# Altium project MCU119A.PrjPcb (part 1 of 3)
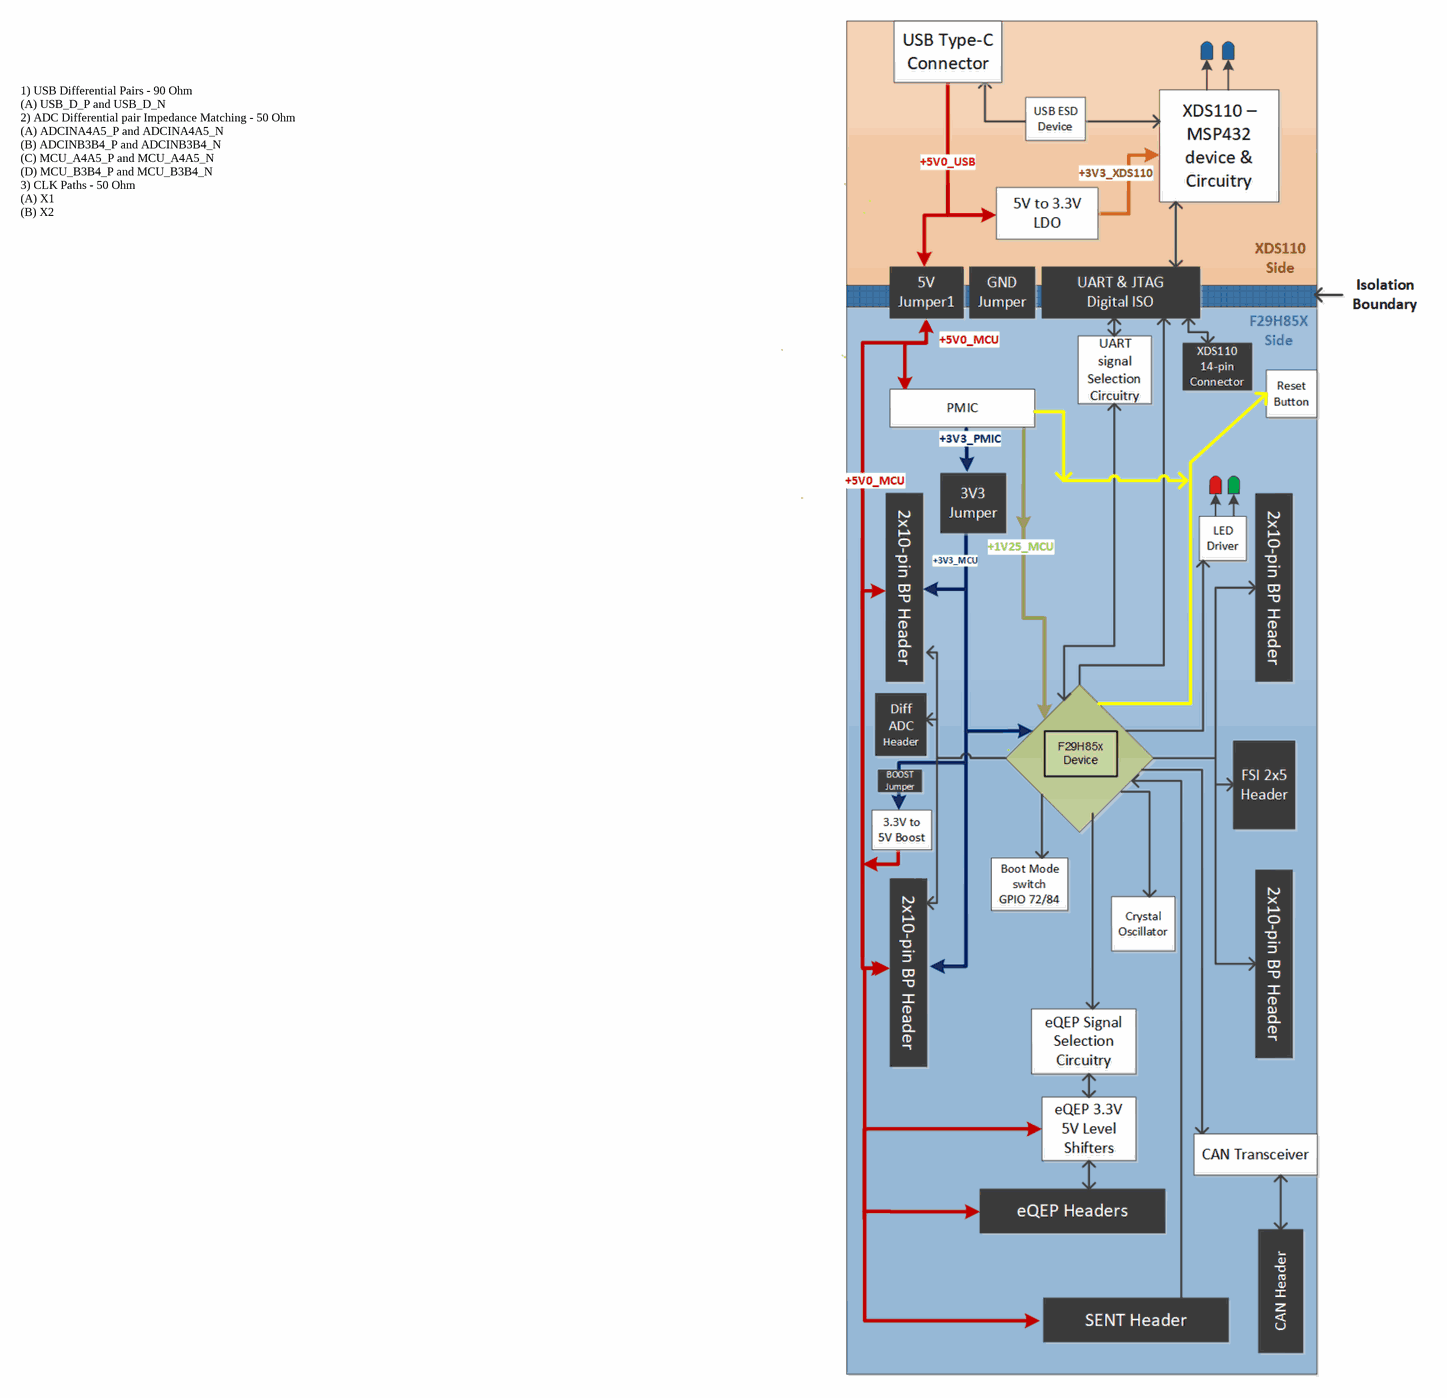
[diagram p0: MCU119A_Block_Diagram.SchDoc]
CopyrightYear: 2024; DrawnBy: Susmitha Bumadi; EVM_orderable: LAUNCHXL-F29H85X; PCB_Layout: a0509580; PCB_Rev: A; PRJ_Customer: Public Release; PRJ_Engineer: Susmitha Bumadi; PRJ_Number: MCU119; PRJ_Title: LAUNCHXL-F29H85X; SCH_Rev: A; TechSupport: http://www.ti.com/support; TID: N/A
8 sheets, 317 parts. Net scope: global (net labels, ports and power ports of the same name join across sheets).
Board file: MCU119A.PcbDoc
Sheets:
  MCU119A_Block_Diagram.SchDoc
  MCU119A_Connectors.SchDoc
  MCU119A_F29H85X_Device.SchDoc
  MCU119A_ADC.SchDoc
  MCU119A_USB_and_Power.SchDoc
  MCU119A_XDS110_MCU.SchDoc
  MCU119A_AltRouting_Misc.SchDoc
  MCU119A_Hardware.SchDoc

## Sheet MCU119A_Block_Diagram.SchDoc
size 431 x 279 mm; Date: Not shown in title block; ApprovedBy: Not shown in title block; CheckedBy: Not shown in title block; Author: Not shown in title block; CompanyName: Not shown in title block; Engineer: Not shown in title block; Organization: Not shown in title block; Address1: Not shown in title block; Address2: Not shown in title block; Address3: Not shown in title block; Address4: Not shown in title block; DocumentNumber: 1; Revision: Use project parameter SCH_Rev; SheetNumber: 1; SheetTotal: 8; PageSetup: Record=PageOptions¦CenterHorizontal=True¦CenterVertical=True¦PrintScale=1.00¦XCorrection=1.00¦YCorrection=1.00¦PrintKind=0¦BorderSize=5000000¦LeftOffset=0¦BottomOffset=0¦Orientation=2¦PaperLength=1000¦PaperWidth=1000¦Scale=100¦PaperSource=15¦PrintQuality=600¦MediaType=1¦DitherType=10¦PaperKind=Letter¦PrintScaleMode=1

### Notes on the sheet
- 1) USB Differential Pairs - 90 Ohm
  (A) USB_D_P and USB_D_N
  2) ADC Differential pair Impedance Matching - 50 Ohm
  (A) ADCINA4A5_P and ADCINA4A5_N
  (B) ADCINB3B4_P and ADCINB3B4_N
  (C) MCU_A4A5_P and MCU_A4A5_N
  (D) MCU_B3B4_P and MCU_B3B4_N
  3) CLK Paths - 50 Ohm
  (A) X1
  (B) X2

## Sheet MCU119A_Connectors.SchDoc
size 431 x 279 mm; Date: Not shown in title block; ApprovedBy: Not shown in title block; CheckedBy: Not shown in title block; Author: Not shown in title block; CompanyName: Not shown in title block; Engineer: Not shown in title block; Organization: Not shown in title block; Address1: Not shown in title block; Address2: Not shown in title block; Address3: Not shown in title block; Address4: Not shown in title block; DocumentNumber: 2; Revision: Use project parameter SCH_Rev; SheetNumber: 2; SheetTotal: 8; PageSetup: Record=PageOptions¦CenterHorizontal=True¦CenterVertical=True¦PrintScale=1.00¦XCorrection=1.00¦YCorrection=1.00¦PrintKind=0¦BorderSize=5000000¦LeftOffset=0¦BottomOffset=0¦Orientation=2¦PaperLength=1000¦PaperWidth=1000¦Scale=100¦PaperSource=15¦PrintQuality=600¦MediaType=1¦DitherType=10¦PaperKind=Letter¦PrintScaleMode=1
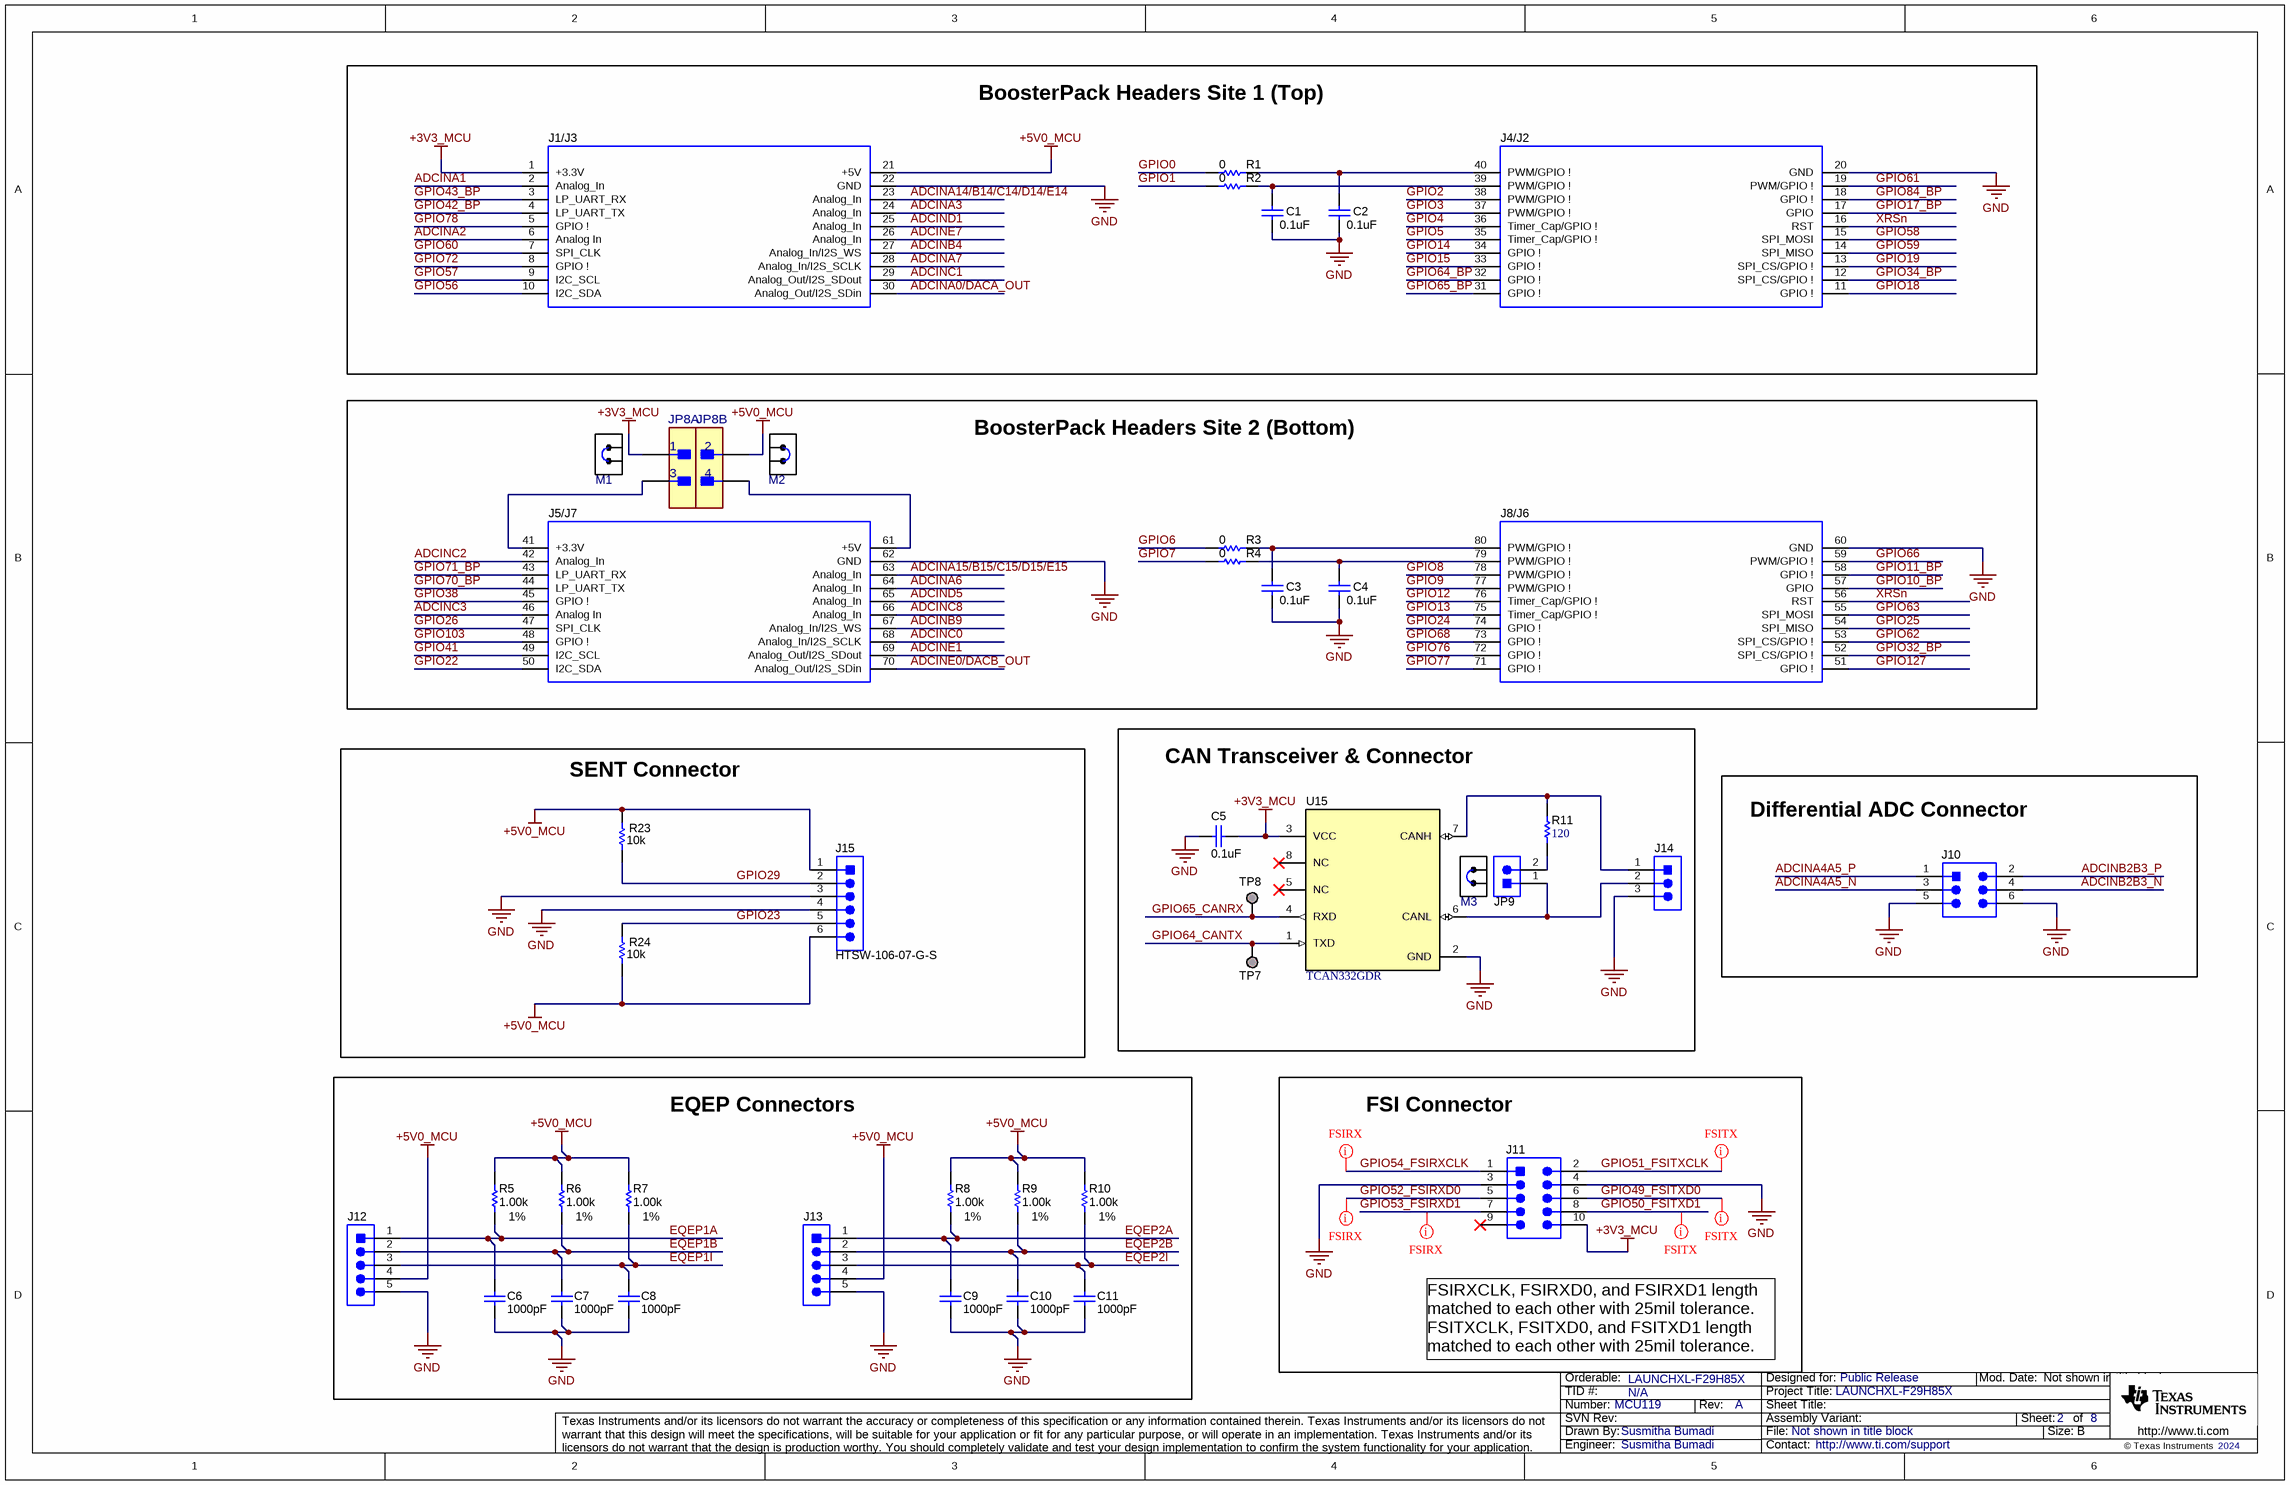
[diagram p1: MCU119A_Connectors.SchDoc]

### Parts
C1  ValueDisplayed: 0.1uF  [0402]  (hidden comment: 885012205037)
C2  ValueDisplayed: 0.1uF  [0402]  (hidden comment: 885012205037)
C3  ValueDisplayed: 0.1uF  [0402]  (hidden comment: 885012205037)
C4  ValueDisplayed: 0.1uF  [0402]  (hidden comment: 885012205037)
C5  ValueDisplayed: 0.1uF  [0402]  (hidden comment: 885012205037)
C6  ValueDisplayed: 1000pF  [0402]  (hidden comment: 885012205061)
C7  ValueDisplayed: 1000pF  [0402]  (hidden comment: 885012205061)
C8  ValueDisplayed: 1000pF  [0402]  (hidden comment: 885012205061)
C9  ValueDisplayed: 1000pF  [0402]  (hidden comment: 885012205061)
C10  ValueDisplayed: 1000pF  [0402]  (hidden comment: 885012205061)
C11  ValueDisplayed: 1000pF  [0402]  (hidden comment: 885012205061)
J1/J3  SSQ-110-03-T-D  [BoosterPack_40pin_J1J3]  (value not drawn)
J4/J2  SSQ-110-03-T-D  [BoosterPack_40pin_J2J4]  (value not drawn)
J5/J7  SSQ-110-03-T-D  [BoosterPack_40pin_J5J7]  (value not drawn)
J8/J6  SSQ-110-03-T-D  [BoosterPack_40pin_J6J8]  (value not drawn)
J10  61300621121  [Wurth_61300621121]  (value not drawn)
J11  61301021121  [WURTH_61301021121]  (value not drawn)
J12  61300511121  [Wurth_61300511121]  (value not drawn)
J13  61300511121  [Wurth_61300511121]  (value not drawn)
J14  61300311121  [WURTH_61300311121]  (value not drawn)
J15  HTSW-106-07-G-S  [FP-HTSW-106-07-G-S_HDR6-MFG]
JP8  61300421121  [FP-61300421121_HDR4-MFG]  (value not drawn)  (parts A,B of 2)
JP9  61300211121  [WURTH_61300211121]  (value not drawn)
M1  60900213421  [Wurth_60900213421]  (value not drawn)
M2  60900213421  [Wurth_60900213421]  (value not drawn)
M3  60900213421  [Wurth_60900213421]  (value not drawn)
R1  ValueDisplayed: 0  [0603]  (hidden comment: ERJ-3GEY0R00V)
R2  ValueDisplayed: 0  [0603]  (hidden comment: ERJ-3GEY0R00V)
R3  ValueDisplayed: 0  [0603]  (hidden comment: ERJ-3GEY0R00V)
R4  ValueDisplayed: 0  [0603]  (hidden comment: ERJ-3GEY0R00V)
R5  ValueDisplayed: 1.00k  Value1: 1%  [0402]  (hidden comment: CRCW04021K00FKED)
R6  ValueDisplayed: 1.00k  Value1: 1%  [0402]  (hidden comment: CRCW04021K00FKED)
R7  ValueDisplayed: 1.00k  Value1: 1%  [0402]  (hidden comment: CRCW04021K00FKED)
R8  ValueDisplayed: 1.00k  Value1: 1%  [0402]  (hidden comment: CRCW04021K00FKED)
R9  ValueDisplayed: 1.00k  Value1: 1%  [0402]  (hidden comment: CRCW04021K00FKED)
R10  ValueDisplayed: 1.00k  Value1: 1%  [0402]  (hidden comment: CRCW04021K00FKED)
R11  ValueDisplayed: 120  [0603]  (hidden comment: RC0603FR-07120RL)
R23  ValueDisplayed: 10k  [0402]  (hidden comment: CRCW040210K0JNED)
R24  ValueDisplayed: 10k  [0402]  (hidden comment: CRCW040210K0JNED)
TP7  TESTPOINT  [TP_50MIL-25MILHOLE]  (value not drawn)  (no BOM)
TP8  TESTPOINT  [TP_50MIL-25MILHOLE]  (value not drawn)  (no BOM)
U15  TCAN332GDR  [D0008A_N]

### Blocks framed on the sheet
BoosterPack Headers Site 1 (Top): C1 C2 J1/J3 J4/J2 R1 R2
BoosterPack Headers Site 2 (Bottom): C3 C4 J5/J7 J8/J6 JP8 M1 M2 R3 R4
SENT Connector: J15 R23 R24
CAN Transceiver & Connector: C5 J14 JP9 M3 R11 TP7 TP8 U15
Differential ADC Connector: J10
EQEP Connectors: C6-C11 J12 J13 R5-R10
FSI Connector: J11

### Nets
+3V3_MCU: C5.2 J1/J3.1(+3.3V) J11.10 JP8.1 U15.3(VCC)
+5V0_MCU: J1/J3.21(+5V) J12.4 J13.4 J15.1 J15.6 JP8.2 R5.2 R6.2 R7.2 R8.2 R9.2 R10.2 R23.2 R24.1
GND: C1.2 C2.2 C3.2 C4.2 C5.1 C6.2 C7.2 C8.2 C9.2 C10.2 C11.2 J1/J3.22(GND) J4/J2.20(GND) J5/J7.62(GND) J8/J6.60(GND) J10.5 J10.6 J11.3 J11.4 J12.5 J13.5 J14.3 J15.3 J15.4 U15.2(GND)
ADCINA0/DACA_OUT: J1/J3.30(Analog_Out/I2S_SDin)
ADCINA1: J1/J3.2(Analog_In)
ADCINA2: J1/J3.6(Analog_In)
ADCINA3: J1/J3.24(Analog_In)
ADCINA4A5_N: J10.3
ADCINA4A5_P: J10.1
ADCINA6: J5/J7.64(Analog_In)
ADCINA7: J1/J3.28(Analog_In/I2S_SCLK)
ADCINA14/B14/C14/D14/E14: J1/J3.23(Analog_In)
ADCINA15/B15/C15/D15/E15: J5/J7.63(Analog_In)
ADCINB2B3_N: J10.4
ADCINB2B3_P: J10.2
ADCINB4: J1/J3.27(Analog_In/I2S_WS)
ADCINB9: J5/J7.67(Analog_In/I2S_WS)
ADCINC0: J5/J7.68(Analog_In/I2S_SCLK)
ADCINC1: J1/J3.29(Analog_Out/I2S_SDout)
ADCINC2: J5/J7.42(Analog_In)
ADCINC3: J5/J7.46(Analog_In)
ADCINC8: J5/J7.66(Analog_In)
ADCIND1: J1/J3.25(Analog_In)
ADCIND5: J5/J7.65(Analog_In)
ADCINE0/DACB_OUT: J5/J7.70(Analog_Out/I2S_SDin)
ADCINE1: J5/J7.69(Analog_Out/I2S_SDout)
ADCINE7: J1/J3.26(Analog_In)
EQEP1A: C6.1 J12.1 R5.1
EQEP1B: C7.1 J12.2 R6.1
EQEP1I: C8.1 J12.3 R7.1
EQEP2A: C9.1 J13.1 R8.1
EQEP2B: C10.1 J13.2 R9.1
EQEP2I: C11.1 J13.3 R10.1
GPIO0: R1.2
GPIO1: R2.2
GPIO2: J4/J2.38(PWM/GPIO_!)
GPIO3: J4/J2.37(PWM/GPIO_!)
GPIO4: J4/J2.36(Timer_Cap/GPIO_!)
GPIO5: J4/J2.35(Timer_Cap/GPIO_!)
GPIO6: R3.2
GPIO7: R4.2
GPIO8: J8/J6.78(PWM/GPIO_!)
GPIO9: J8/J6.77(PWM/GPIO_!)
GPIO10_BP: J8/J6.57(GPIO)
GPIO11_BP: J8/J6.58(GPIO_!)
GPIO12: J8/J6.76(Timer_Cap/GPIO_!)
GPIO13: J8/J6.75(Timer_Cap/GPIO_!)
GPIO14: J4/J2.34(GPIO_!)
GPIO15: J4/J2.33(GPIO_!)
GPIO17_BP: J4/J2.17(GPIO)
GPIO18: J4/J2.11(GPIO_!)
GPIO19: J4/J2.13(SPI_CS/GPIO_!)
GPIO22: J5/J7.50(I2C_SDA)
GPIO23: J15.5 R24.2
GPIO24: J8/J6.74(GPIO_!)
GPIO25: J8/J6.54(SPI_MISO)
GPIO26: J5/J7.47(SPI_CLK)
GPIO29: J15.2 R23.1
GPIO32_BP: J8/J6.52(SPI_CS/GPIO_!)
GPIO34_BP: J4/J2.12(SPI_CS/GPIO_!)
GPIO38: J5/J7.45(GPIO_!)
GPIO41: J5/J7.49(I2C_SCL)
GPIO42_BP: J1/J3.4(LP_UART_TX)
GPIO43_BP: J1/J3.3(LP_UART_RX)
GPIO49_FSITXD0: J11.6
GPIO50_FSITXD1: J11.8
GPIO51_FSITXCLK: J11.2
GPIO52_FSIRXD0: J11.5
GPIO53_FSIRXD1: J11.7
GPIO54_FSIRXCLK: J11.1
GPIO56: J1/J3.10(I2C_SDA)
GPIO57: J1/J3.9(I2C_SCL)
GPIO58: J4/J2.15(SPI_MOSI)
GPIO59: J4/J2.14(SPI_MISO)
GPIO60: J1/J3.7(SPI_CLK)
GPIO61: J4/J2.19(PWM/GPIO_!)
GPIO62: J8/J6.53(SPI_CS/GPIO_!)
GPIO63: J8/J6.55(SPI_MOSI)
GPIO64_BP: J4/J2.32(GPIO_!)
GPIO64_CANTX: TP7.1 U15.1(TXD)
GPIO65_BP: J4/J2.31(GPIO_!)
GPIO65_CANRX: TP8.1 U15.4(RXD)
GPIO66: J8/J6.59(PWM/GPIO_!)
GPIO68: J8/J6.73(GPIO_!)
GPIO70_BP: J5/J7.44(LP_UART_TX)
GPIO71_BP: J5/J7.43(LP_UART_RX)
GPIO72: J1/J3.8(GPIO_!)
GPIO76: J8/J6.72(GPIO_!)
GPIO77: J8/J6.71(GPIO_!)
GPIO78: J1/J3.5(GPIO_!)
GPIO84_BP: J4/J2.18(GPIO_!)
GPIO103: J5/J7.48(GPIO_!)
GPIO127: J8/J6.51(GPIO_!)
XRSn: J4/J2.16(RST) J8/J6.56(RST)
NetC1_1: C1.1 J4/J2.39(PWM/GPIO_!) R2.1
NetC2_1: C2.1 J4/J2.40(PWM/GPIO_!) R1.1
NetC3_1: C3.1 J8/J6.80(PWM/GPIO_!) R3.1
NetC4_1: C4.1 J8/J6.79(PWM/GPIO_!) R4.1
NetJ5/J7_41: J5/J7.41(+3.3V) JP8.3
NetJ5/J7_61: J5/J7.61(+5V) JP8.4
NetJ14_1: J14.1 R11.2 U15.7(CANH)
NetJ14_2: J14.2 JP9.1 U15.6(CANL)
NetJP9_2: JP9.2 R11.1

Not connected (* = marked no-connect by the designer): J11 9*; U15 5(NC)* 8(NC)*

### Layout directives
net class FSIRX: GPIO52_FSIRXD0, GPIO53_FSIRXD1, GPIO54_FSIRXCLK
net class FSITX: GPIO49_FSITXD0, GPIO50_FSITXD1, GPIO51_FSITXCLK

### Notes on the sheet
- FSIRXCLK, FSIRXD0, and FSIRXD1 length matched to each other with 25mil tolerance.
  FSITXCLK, FSITXD0, and FSITXD1 length matched to each other with 25mil tolerance.

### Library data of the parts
C1-C5 = CMP-0006228-2: CAP, CERM, 0.1 uF, 16 V, +/- 10%, X7R, 0402; Manufacturer: Wurth Elektronik; TaMin_C: -55°C; Polarized: N; SizeAreaWB_mm2: 3; Value1: Unknown; U/M: EA; Value: 0.1uF; TaMax_C: 125°C; SizeZ_mm: 0.6; SizeX_mm: 1; SizeY_mm: 0.5; Value2: 16V; Cap_F: 100nF; AEC Category: Q200
C6-C11 = CMP-0006231-2: CAP, CERM, 1000 pF, 50 V, +/- 10%, X7R, 0402; Manufacturer: Wurth Elektronik; Polarized: N; Value: 1000pF; U/M: EA; Cap_F: 1nF; Value1: Unknown; VDC_V: 50V; TaMin_C: -55°C; TaMax_C: 125°C; SizeArea_mm2: 0.5; SizeAreaWB_mm2: 3; SizeX_mm: 1; SizeZ_mm: 0.6; AEC Category: Q200
J1/J3 = CMP-0003837-4: Receptacle, 2.54mm, 10x2, Tin, TH; Alternate PartNumber: CRD-081413-A-G; Manufacturer: Samtec; Alternate Manufacturer: Major League Electronics; Note: Booster Pack 40 pin J1 and J3; Green_Lifecycle: Active; Green_REACh: Incomplete
J4/J2 = CMP-0078266-4: Receptacle, 2.54mm, 10x2, Tin, TH; Alternate PartNumber: CRD-081413-A-G; Manufacturer: Samtec; Alternate Manufacturer: Major League Electronics; Note: Booster Pack 40 pin J2 and J4; Green_REACh: Incomplete; Green_Lifecycle: Active
J5/J7 = CMP-0081070-3: Receptacle, 2.54mm, 10x2, Tin, TH; Alternate PartNumber: CRD-081413-A-G; Manufacturer: Samtec; Alternate Manufacturer: Major League Electronics; Note: Booster Pack 40 pin J5 and J7; Green_REACh: Incomplete; Green_Lifecycle: Active
J8/J6 = CMP-0081071-3: Receptacle, 2.54mm, 10x2, Tin, TH; Alternate PartNumber: CRD-081413-A-G; Manufacturer: Samtec; Alternate Manufacturer: Major League Electronics; Note: Booster Pack 40 pin J6 and J8; Green_REACh: Incomplete; Green_Lifecycle: Active
J10 = CMP-0054802-2: Header, 2.54mm, 3x2, Gold, TH; Manufacturer: Wurth Elektronik; Green_Lifecycle: Active; Shrouded: N; Gender: Male; Green_REACh: Passed; Row_Count: 2; RowSpacing_mm: 2.54
J11 = CMP-0054806-3: Header, 2.54 mm, 5x2, Gold, TH; Manufacturer: Wurth Elektronik; Green_Lifecycle: Active; Green_REACh: Passed; Cert_UL: Y; Current_A: 3A; Gender: Male; Pitch_mm: 2.54; Row_Count: 2; Shrouded: N; Voltage_V: 250V
J12 J13 = CMP-0084909-1: Header, 2.54mm, 5x1, Gold, TH; Manufacturer: Wurth Elektronik; Pitch_mm: 2.54; Gender: Male; Row_Count: 1; Shrouded: N; Current_A: 3A; Voltage_V: 250V
J14 = CMP-0054796-4: Header, 2.54 mm, 3x1, Gold, TH; Manufacturer: Wurth Elektronik; Green_Lifecycle: Active; Green_REACh: Passed; CNHeader: TRUE; CT: FALSE
J15 = CMP-0095629-2: Connector Header Through Hole 6 position 0.100" (2.54mm); Manufacturer: Samtec; Voltage_V: 550V; ContactFinish: Gold,Nickel; SizeZ_mm: 8.71mm; Row_Count: 1; Conn Gender: Male; Conn Orientation: Vertical; AEC Qualified: No; Current_A: 6.3A
JP8 = CMP-0092422-1: THT Vertical Pin Header WR-PHD, Pitch 2.54 mm, Dual Row, 4 pins; Manufacturer: Wurth Electronics; DUT-Pitch_mm: 2.54mm; SizeZ_mm: 8.89mm; Voltage_V: 250V; Conn Gender: Male; AEC Qualified: No; Row_Count: 2; ContactFinish: Gold; Conn Orientation: Straight; Current_A: 3A
JP9 = CMP-0054794-2: Header, 2.54 mm, 2x1, Gold, TH; Manufacturer: Wurth Elektronik; Pitch_mm: 2.54; Gender: Male; Shrouded: N; Row_Count: 1; Cert_UL: Y; Green_Lifecycle: Active; Green_REACh: Passed
M1-M3 = CMP-0003761-2: Shunt, 2.54mm, Gold, Black; Manufacturer: Wurth Elektronik
R1-R4 = CMP-0025874-4: RES, 0, 5%, 0.1 W, AEC-Q200 Grade 0, 0603; Manufacturer: Panasonic; Power_W: 100mW; TempCo: 600 ppm/C; Value_Code: 0000; Value: 0; EIA_Code: E24; SizeX_mm: 1.6; SizeY_mm: 0.8; SizeZ_mm: 1; Value2: 0.1W; SizeArea_mm2: 1.28; AEC Qualified: Y; VDC_V: 50V; AEC Category: Q200; SizeAreaWB_mm2: 4.68
R5-R10 = CMP-0026071-3: RES, 1.00 k, 1%, 0.063 W, AEC-Q200 Grade 0, 0402; Manufacturer: Vishay-Dale; Value: 1.00k; Res_ohm: 1k; Value_Code: 1k00; Power_W: 63mW; Value2: 0.063W; VDC_V: 50V; TempCo: 100 ppm/C; SizeArea_mm2: 0.5; SizeX_mm: 1; SizeZ_mm: 0.6; EIA_Code: E96; AEC Category: Q200; AEC Qualified: Y; AEC Grade: 0
R11 = CMP-0022769-5: RES, 120, 1%, 0.1 W, 0603; Manufacturer: Yageo; Value: 120; Value_Code: 120R; Power_W: 100mW; Value2: 0.1W; VDC_V: 75V; TempCo: 100 ppm/C; SizeArea_mm2: 1.28; SizeX_mm: 1.6; SizeY_mm: 0.8; SizeZ_mm: 1; AEC Category: Q200; AEC Qualified: N; SizeAreaWB_mm2: 4.68
R23 R24 = CMP-0026890-5: RES, 10 k, 5%, 0.063 W, AEC-Q200 Grade 0, 0402; PartNumber: CRCW04022K20JNED; Manufacturer: Vishay-Dale; Value: 2.2k; Value_Code: 2k20; Power_W: 63mW; Value2: 0.063W; VDC_V: 50V; TempCo: 200 ppm/C; SizeArea_mm2: 0.5; SizeX_mm: 1; SizeZ_mm: 0.6; EIA_Code: E24; AEC Category: Q200; AEC Qualified: Y; AEC Grade: 0
TP7 TP8 = CMP-0078143-4: TEST POINT.  No entry in BOM.
U15 = CMP-0080978-2: 3.3-V CAN Transceivers with CAN FD (Flexible Data Rate), D0008A (SOIC-8); Alternate Manufacturer: Texas Instruments; SizeAreaWB_mm2: 56.58; SizeZ_mm: 1.75; SizeX_mm: 4.9; SizeY_mm: 6.2; SizeArea_mm2: 30.38; CompType: IC; AEC Qualified: N; AEC Category: Q200

## Sheet MCU119A_F29H85X_Device.SchDoc
size 431 x 279 mm; Date: Not shown in title block; ApprovedBy: Not shown in title block; CheckedBy: Not shown in title block; Author: Not shown in title block; CompanyName: Not shown in title block; Engineer: Not shown in title block; Organization: Not shown in title block; Address1: Not shown in title block; Address2: Not shown in title block; Address3: Not shown in title block; Address4: Not shown in title block; DocumentNumber: 4; Revision: Use project parameter SCH_Rev; SheetNumber: 3; SheetTotal: 8; PageSetup: Record=PageOptions¦CenterHorizontal=True¦CenterVertical=True¦PrintScale=1.00¦XCorrection=1.00¦YCorrection=1.00¦PrintKind=0¦BorderSize=5000000¦LeftOffset=0¦BottomOffset=0¦Orientation=2¦PaperLength=1000¦PaperWidth=1000¦Scale=100¦PaperSource=15¦PrintQuality=600¦MediaType=1¦DitherType=10¦PaperKind=Letter¦PrintScaleMode=1
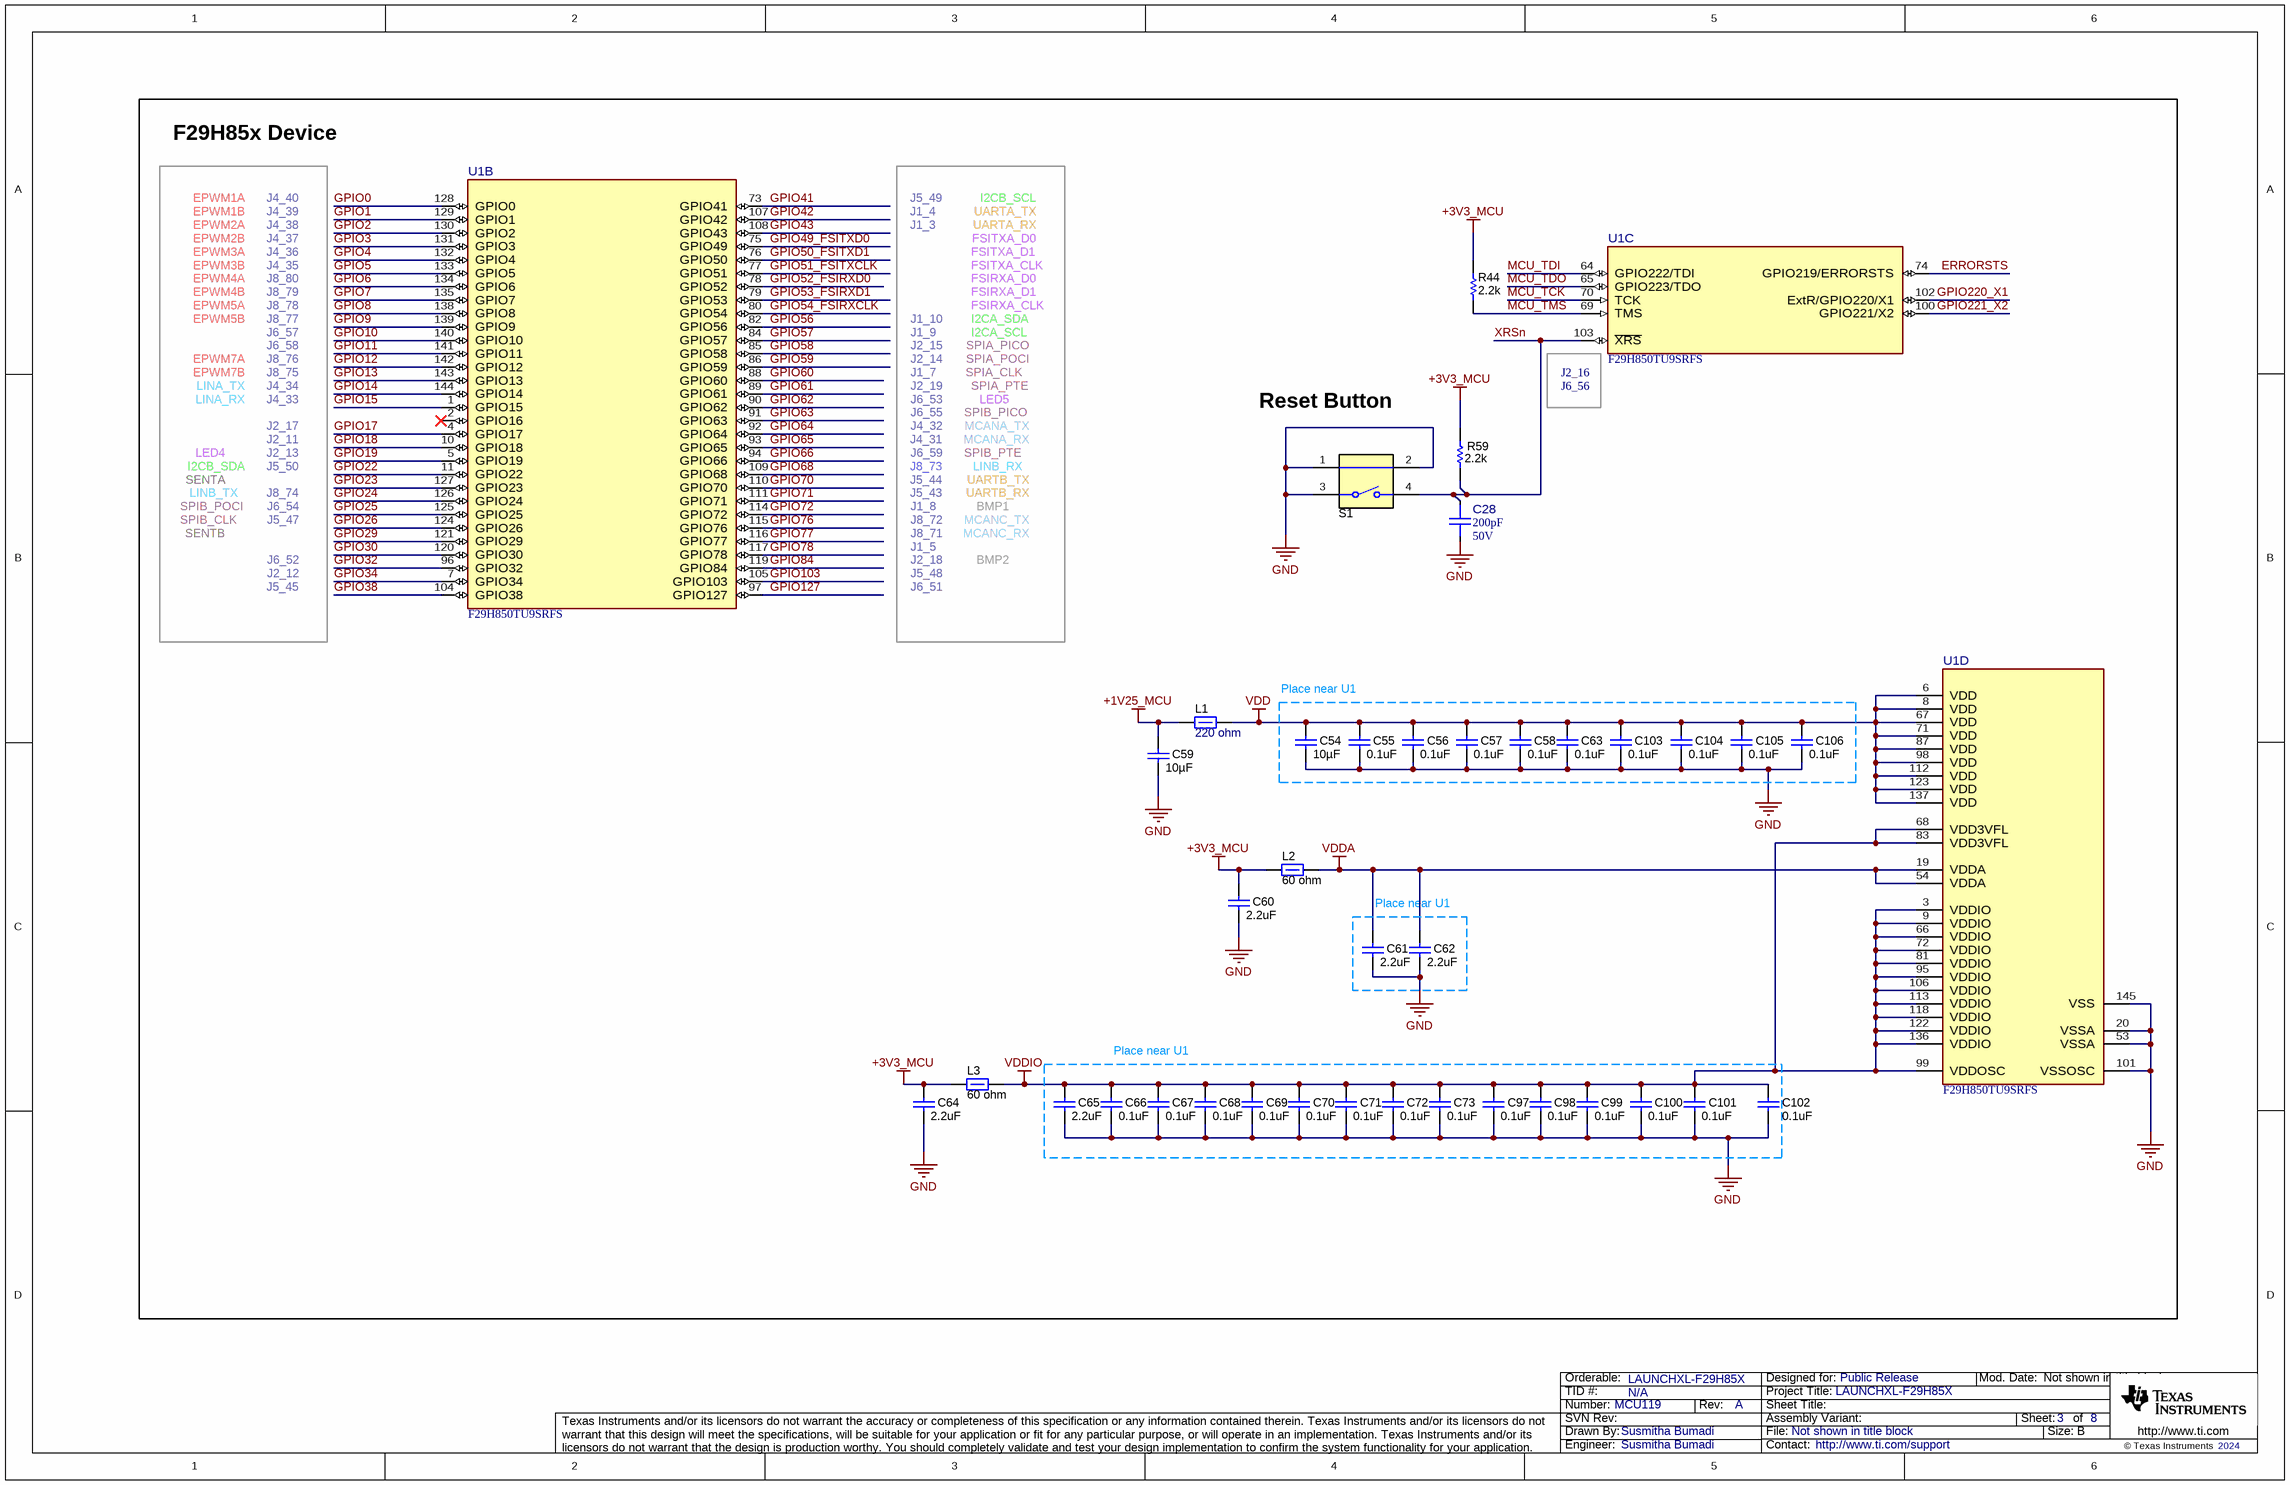
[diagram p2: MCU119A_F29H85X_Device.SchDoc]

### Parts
C28  ValueDisplayed: 200pF  VDC_V: 50V  [FP-GCM1555C1H201FA16D_0402-MFG]  (hidden comment: GCM1555C1H201FA16D)
C54  ValueDisplayed: 10µF  [0603]  (hidden comment: GRM188R61C106KAALD)
C55  ValueDisplayed: 0.1uF  [0402]  (hidden comment: 885012205037)
C56  ValueDisplayed: 0.1uF  [0402]  (hidden comment: 885012205037)
C57  ValueDisplayed: 0.1uF  [0402]  (hidden comment: 885012205037)
C58  ValueDisplayed: 0.1uF  [0402]  (hidden comment: 885012205037)
C59  ValueDisplayed: 10µF  [0603]  (hidden comment: GRM188R61C106KAALD)
C60  ValueDisplayed: 2.2uF  [0603]  (hidden comment: 885012106018)
C61  ValueDisplayed: 2.2uF  [0603]  (hidden comment: 885012106018)
C62  ValueDisplayed: 2.2uF  [0603]  (hidden comment: 885012106018)
C63  ValueDisplayed: 0.1uF  [0402]  (hidden comment: 885012205037)
C64  ValueDisplayed: 2.2uF  [0603]  (hidden comment: 885012106018)
C65  ValueDisplayed: 2.2uF  [0603]  (hidden comment: 885012106018)
C66  ValueDisplayed: 0.1uF  [0402]  (hidden comment: 885012205037)
C67  ValueDisplayed: 0.1uF  [0402]  (hidden comment: 885012205037)
C68  ValueDisplayed: 0.1uF  [0402]  (hidden comment: 885012205037)
C69  ValueDisplayed: 0.1uF  [0402]  (hidden comment: 885012205037)
C70  ValueDisplayed: 0.1uF  [0402]  (hidden comment: 885012205037)
C71  ValueDisplayed: 0.1uF  [0402]  (hidden comment: 885012205037)
C72  ValueDisplayed: 0.1uF  [0402]  (hidden comment: 885012205037)
C73  ValueDisplayed: 0.1uF  [0402]  (hidden comment: 885012205037)
C97  ValueDisplayed: 0.1uF  [0402]  (hidden comment: 885012205037)
C98  ValueDisplayed: 0.1uF  [0402]  (hidden comment: 885012205037)
C99  ValueDisplayed: 0.1uF  [0402]  (hidden comment: 885012205037)
C100  ValueDisplayed: 0.1uF  [0402]  (hidden comment: 885012205037)
C101  ValueDisplayed: 0.1uF  [0402]  (hidden comment: 885012205037)
C102  ValueDisplayed: 0.1uF  [0402]  (hidden comment: 885012205037)
C103  ValueDisplayed: 0.1uF  [0402]  (hidden comment: 885012205037)
C104  ValueDisplayed: 0.1uF  [0402]  (hidden comment: 885012205037)
C105  ValueDisplayed: 0.1uF  [0402]  (hidden comment: 885012205037)
C106  ValueDisplayed: 0.1uF  [0402]  (hidden comment: 885012205037)
L1  value 220 ohm  [0805_HV]  (hidden comment: BLM21PG221SN1D)
L2  60 ohm  [0805_HV]
L3  60 ohm  [0805_HV]
R44  ValueDisplayed: 2.2k  [0402]  (hidden comment: CRCW04022K20JNED)
R59  ValueDisplayed: 2.2k  [0402]  (hidden comment: CRCW04022K20JNED)
S1  1188E-1K2-V-TR  [SW_1188E]  (value not drawn)
U1  F29H850TU9SRFS  [RFS0144A-MFG]  (parts B,C,D of 4)

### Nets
+1V25_MCU: C59.1 L1.1
+3V3_MCU: C60.1 C64.1 L2.1 L3.1 R44.2 R59.2
GND: C28.2 C54.2 C55.2 C56.2 C57.2 C58.2 C59.2 C60.2 C61.2 C62.2 C63.2 C64.2 C65.2 C66.2 C67.2 C68.2 C69.2 C70.2 C71.2 C72.2 C73.2 C97.2 C98.2 C99.2 C100.2 C101.2 C102.2 C103.2 C104.2 C105.2 C106.2 S1.1 S1.2 S1.3 U1.20(VSSA) U1.53(VSSA) U1.101(VSSOSC) U1.145(VSS)
VDD: C54.1 C55.1 C56.1 C57.1 C58.1 C63.1 C103.1 C104.1 C105.1 C106.1 L1.2 U1.6(VDD) U1.8(VDD) U1.67(VDD) U1.71(VDD) U1.87(VDD) U1.98(VDD) U1.112(VDD) U1.123(VDD) U1.137(VDD)
VDDA: C61.1 C62.1 L2.2 U1.19(VDDA) U1.54(VDDA)
VDDIO: C65.1 C66.1 C67.1 C68.1 C69.1 C70.1 C71.1 C72.1 C73.1 C97.1 C98.1 C99.1 C100.1 C101.1 C102.1 L3.2 U1.3(VDDIO) U1.9(VDDIO) U1.66(VDDIO) U1.68(VDD3VFL) U1.72(VDDIO) U1.81(VDDIO) U1.83(VDD3VFL) U1.95(VDDIO) U1.99(VDDOSC) U1.106(VDDIO) U1.113(VDDIO) U1.118(VDDIO) U1.122(VDDIO) U1.136(VDDIO)
ERRORSTS: U1.74(GPIO219/ERRORSTS)
GPIO0: U1.128(GPIO0)
GPIO1: U1.129(GPIO1)
GPIO2: U1.130(GPIO2)
GPIO3: U1.131(GPIO3)
GPIO4: U1.132(GPIO4)
GPIO5: U1.133(GPIO5)
GPIO6: U1.134(GPIO6)
GPIO7: U1.135(GPIO7)
GPIO8: U1.138(GPIO8)
GPIO9: U1.139(GPIO9)
GPIO10: U1.140(GPIO10)
GPIO11: U1.141(GPIO11)
GPIO12: U1.142(GPIO12)
GPIO13: U1.143(GPIO13)
GPIO14: U1.144(GPIO14)
GPIO15: U1.1(GPIO15)
GPIO17: U1.4(GPIO17)
GPIO18: U1.10(GPIO18)
GPIO19: U1.5(GPIO19)
GPIO22: U1.11(GPIO22)
GPIO23: U1.127(GPIO23)
GPIO24: U1.126(GPIO24)
GPIO25: U1.125(GPIO25)
GPIO26: U1.124(GPIO26)
GPIO29: U1.121(GPIO29)
GPIO30: U1.120(GPIO30)
GPIO32: U1.96(GPIO32)
GPIO34: U1.7(GPIO34)
GPIO38: U1.104(GPIO38)
GPIO41: U1.73(GPIO41)
GPIO42: U1.107(GPIO42)
GPIO43: U1.108(GPIO43)
GPIO49_FSITXD0: U1.75(GPIO49)
GPIO50_FSITXD1: U1.76(GPIO50)
GPIO51_FSITXCLK: U1.77(GPIO51)
GPIO52_FSIRXD0: U1.78(GPIO52)
GPIO53_FSIRXD1: U1.79(GPIO53)
GPIO54_FSIRXCLK: U1.80(GPIO54)
GPIO56: U1.82(GPIO56)
GPIO57: U1.84(GPIO57)
GPIO58: U1.85(GPIO58)
GPIO59: U1.86(GPIO59)
GPIO60: U1.88(GPIO60)
GPIO61: U1.89(GPIO61)
GPIO62: U1.90(GPIO62)
GPIO63: U1.91(GPIO63)
GPIO64: U1.92(GPIO64)
GPIO65: U1.93(GPIO65)
GPIO66: U1.94(GPIO66)
GPIO68: U1.109(GPIO68)
GPIO70: U1.110(GPIO70)
GPIO71: U1.111(GPIO71)
GPIO72: U1.114(GPIO72)
GPIO76: U1.115(GPIO76)
GPIO77: U1.116(GPIO77)
GPIO78: U1.117(GPIO78)
GPIO84: U1.119(GPIO84)
GPIO103: U1.105(GPIO103)
GPIO127: U1.97(GPIO127)
GPIO220_X1: U1.102(ExtR/GPIO220/X1)
GPIO221_X2: U1.100(GPIO221/X2)
MCU_TCK: U1.70(TCK)
MCU_TDI: U1.64(GPIO222/TDI)
MCU_TDO: U1.65(GPIO223/TDO)
MCU_TMS: R44.1 U1.69(TMS)
XRSn: C28.1 R59.1 S1.4 U1.103(~{XRS})

Not connected (* = marked no-connect by the designer): U1 2(GPIO16)*

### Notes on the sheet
- F29H85x Device
- EPWM1A
- EPWM1B
- EPWM2A
- J4_40
- J4_38
- J4_39
- J1_4
- J1_3
- J5_49
- I2CB_SCL
- UARTA_RX
- UARTA_TX
- EPWM3A
- EPWM3B
- EPWM4A
- EPWM4B
- EPWM2B
- J8_79
- J8_80
- J4_37
- J4_36
- J4_35
- FSIRXA_D0
- FSITXA_CLK
- FSITXA_D1
- FSIRXA_D1
- FSITXA_D0
- EPWM7A
- EPWM5A
- EPWM5B
- J6_58
- J8_78
- J8_77
- J6_57
- J8_76
- J1_10
- J1_9
- J2_14
- J2_15
- I2CA_SCL
- I2CA_SDA
- FSIRXA_CLK
- SPIA_POCI
- SPIA_PICO
- EPWM7B
- LINA_TX
- LINA_RX
- J4_33
- J4_34
- J2_17
- J8_75
- J1_7
- J2_19
- J6_53
- J6_55
- J4_32
- SPIB_PICO
- SPIA_PTE
- LED5
- SPIA_CLK
- MCANA_TX
- Reset Button
- (near U1) J2_16
- (near U1) J6_56
- SENTA
- LED4
- LINB_TX
- I2CB_SDA
- J2_11
- J2_13
- J5_50
- J8_74
- J6_59
- J4_31
- J8_73
- J5_44
- J5_43
- SPIB_PTE
- LINB_RX
- MCANA_RX
- UARTB_TX
- UARTB_RX
- SPIB_POCI
- SPIB_CLK
- SENTB
- J5_47
- J6_52
- J6_54
- J8_72
- J1_5
- J8_71
- J1_8
- J2_18
- BMP1
- BMP2
- MCANC_TX
- MCANC_RX
- J2_12
- J5_45
- J5_48
- J6_51
- Place near U1

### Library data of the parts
C28 = CMP-0123381-1: Ceramic Capacitor for Automotive 200pF ±1% 50VDC C0G 0402 Paper T/R; Manufacturer: Murata; AEC Grade: Grade 1; AEC Qualified: Yes; SizeZ_mm: 0.55mm; TempCo: 30ppm/°C; Tolerance_%: 0.01%
C54 C59 = CMP-0086225-1: CAP, CERM, 10 µF, 16 V,+/- 10%, X5R, 0603; Manufacturer: MuRata; SizeZ_mm: 1; SizeX_mm: 1.6; SizeArea_mm2: 1.28; VDC_V: 16V; U/M: EA; AEC Category: Q200; SizeY_mm: 0.8; Polarized: N; TaMax_C: 85°C; Value: 10uF; SizeAreaWB_mm2: 4.68; TaMin_C: -55°C
C55-C58 C63 C66-C73 C97-C106 = CMP-0006228-2: as C1 on sheet MCU119A_Connectors
C60-C62 C64 C65 = CMP-0006825-5: CAP, CERM, 2.2 uF, 16 V, +/- 20%, X5R, 0603; Manufacturer: Wurth Elektronik; TaMin_C: -55°C; Polarized: N; SizeAreaWB_mm2: 4.68; Value1: Unknown; U/M: EA; Value: 2.2uF; TaMax_C: 85°C; SizeZ_mm: 1; SizeX_mm: 1.6; SizeY_mm: 0.8; Value2: 16V; SizeArea_mm2: 1.28; Cap_F: 2.2µF; AEC Category: Q200
L1 = CMP-0003363-1: Ferrite Bead, 220 ohm @ 100 MHz, 2 A, 0805; Manufacturer: MuRata; Imax_A: 2A; DCR_ohm: 45m; Value1: 0.045 ohm; ZTyp@100MHz_Ohm: 220; SizeArea_mm2: 2.5; SizeAreaWB_mm2: 6.75; SizeX_mm: 2; SizeY_mm: 1.25; SizeZ_mm: 1.45
L2 L3 = CMP-0003093-1: Ferrite Bead, 60 ohm @ 100 MHz, 3 A, 0805; Manufacturer: Wurth Elektronik; PartNumber: 742792063; Ztyp@1GHz_Ohm: 95.384; ZTyp@100MHz_Ohm: 60; SizeAreaWB_mm2: 6.75; DCR_ohm: 0.025; Value1: 0.025 ohm; Imax_A: 3A; SizeZ_mm: 1.45; SizeX_mm: 2; SizeY_mm: 1.25; SizeArea_mm2: 2.5
R44 R59 = CMP-0026890-5: RES, 2.2 k, 5%, 0.063 W, AEC-Q200 Grade 0, 0402; Manufacturer: Vishay-Dale; Value: 2.2k; Value_Code: 2k20; Power_W: 63mW; Value2: 0.063W; VDC_V: 50V; TempCo: 200 ppm/C; SizeArea_mm2: 0.5; SizeX_mm: 1; SizeZ_mm: 0.6; EIA_Code: E24; AEC Category: Q200; AEC Qualified: Y; AEC Grade: 0
S1 = CMP-0002328-1: Switch, SPST, 0.05 A, 12 VDC, SMD; Manufacturer: Diptronics; SizeAreaWB_mm2: 53.9; SizeArea_mm2: 27.3; SizeX_mm: 7.8; SizeY_mm: 3.5; VDC_V: 12V; PositionCount: 1; CurrentRating_mA: 50A
U1 = CMP-0121584-3: Real-Time Microcontroller, HTQFP144; Manufacturer: Texas Instruments; SizeZ_mm: 1.2mm; AEC Qualified: No; Core Architecture: C29x; Data Bus Width: 64bits; Frequency_Fixed: 200MHz; Interface: I2C,SPI,UART,CAN,LIN,IrDA,Ethernet,Other; Max Supply Voltage: 3.63V; Memory Size: 4MBytes; Memory Type: FLASH; Min Supply Voltage: 1.14V; Number Of A/D Converters: 5; Number Of Cores: 3; Number Of Ethernet Channels: 1; Number Of I/Os: 81; Number Of I2C Channels: 2; Number Of Pwm Channels: 36; Number Of Timers/Counters: 9; Number Of Uart Channels: 8; Ram Size: 452KBytes; Standoff Height: 0.05mm; TaMax_C: +105°C; TaMin_C: -40°C; TJmax_C: +150°C; AEC Category: Q200; CompType: IC

## Sheet MCU119A_ADC.SchDoc
size 431 x 279 mm; Date: Not shown in title block; ApprovedBy: Not shown in title block; CheckedBy: Not shown in title block; Author: Not shown in title block; CompanyName: Not shown in title block; Engineer: Not shown in title block; Organization: Not shown in title block; Address1: Not shown in title block; Address2: Not shown in title block; Address3: Not shown in title block; Address4: Not shown in title block; DocumentNumber: 5; Revision: Use project parameter SCH_Rev; SheetNumber: 4; SheetTotal: 8; PageSetup: Record=PageOptions¦CenterHorizontal=True¦CenterVertical=True¦PrintScale=1.00¦XCorrection=1.00¦YCorrection=1.00¦PrintKind=0¦BorderSize=5000000¦LeftOffset=0¦BottomOffset=0¦Orientation=2¦PaperLength=1000¦PaperWidth=1000¦Scale=100¦PaperSource=15¦PrintQuality=600¦MediaType=1¦DitherType=10¦PaperKind=Letter¦PrintScaleMode=1
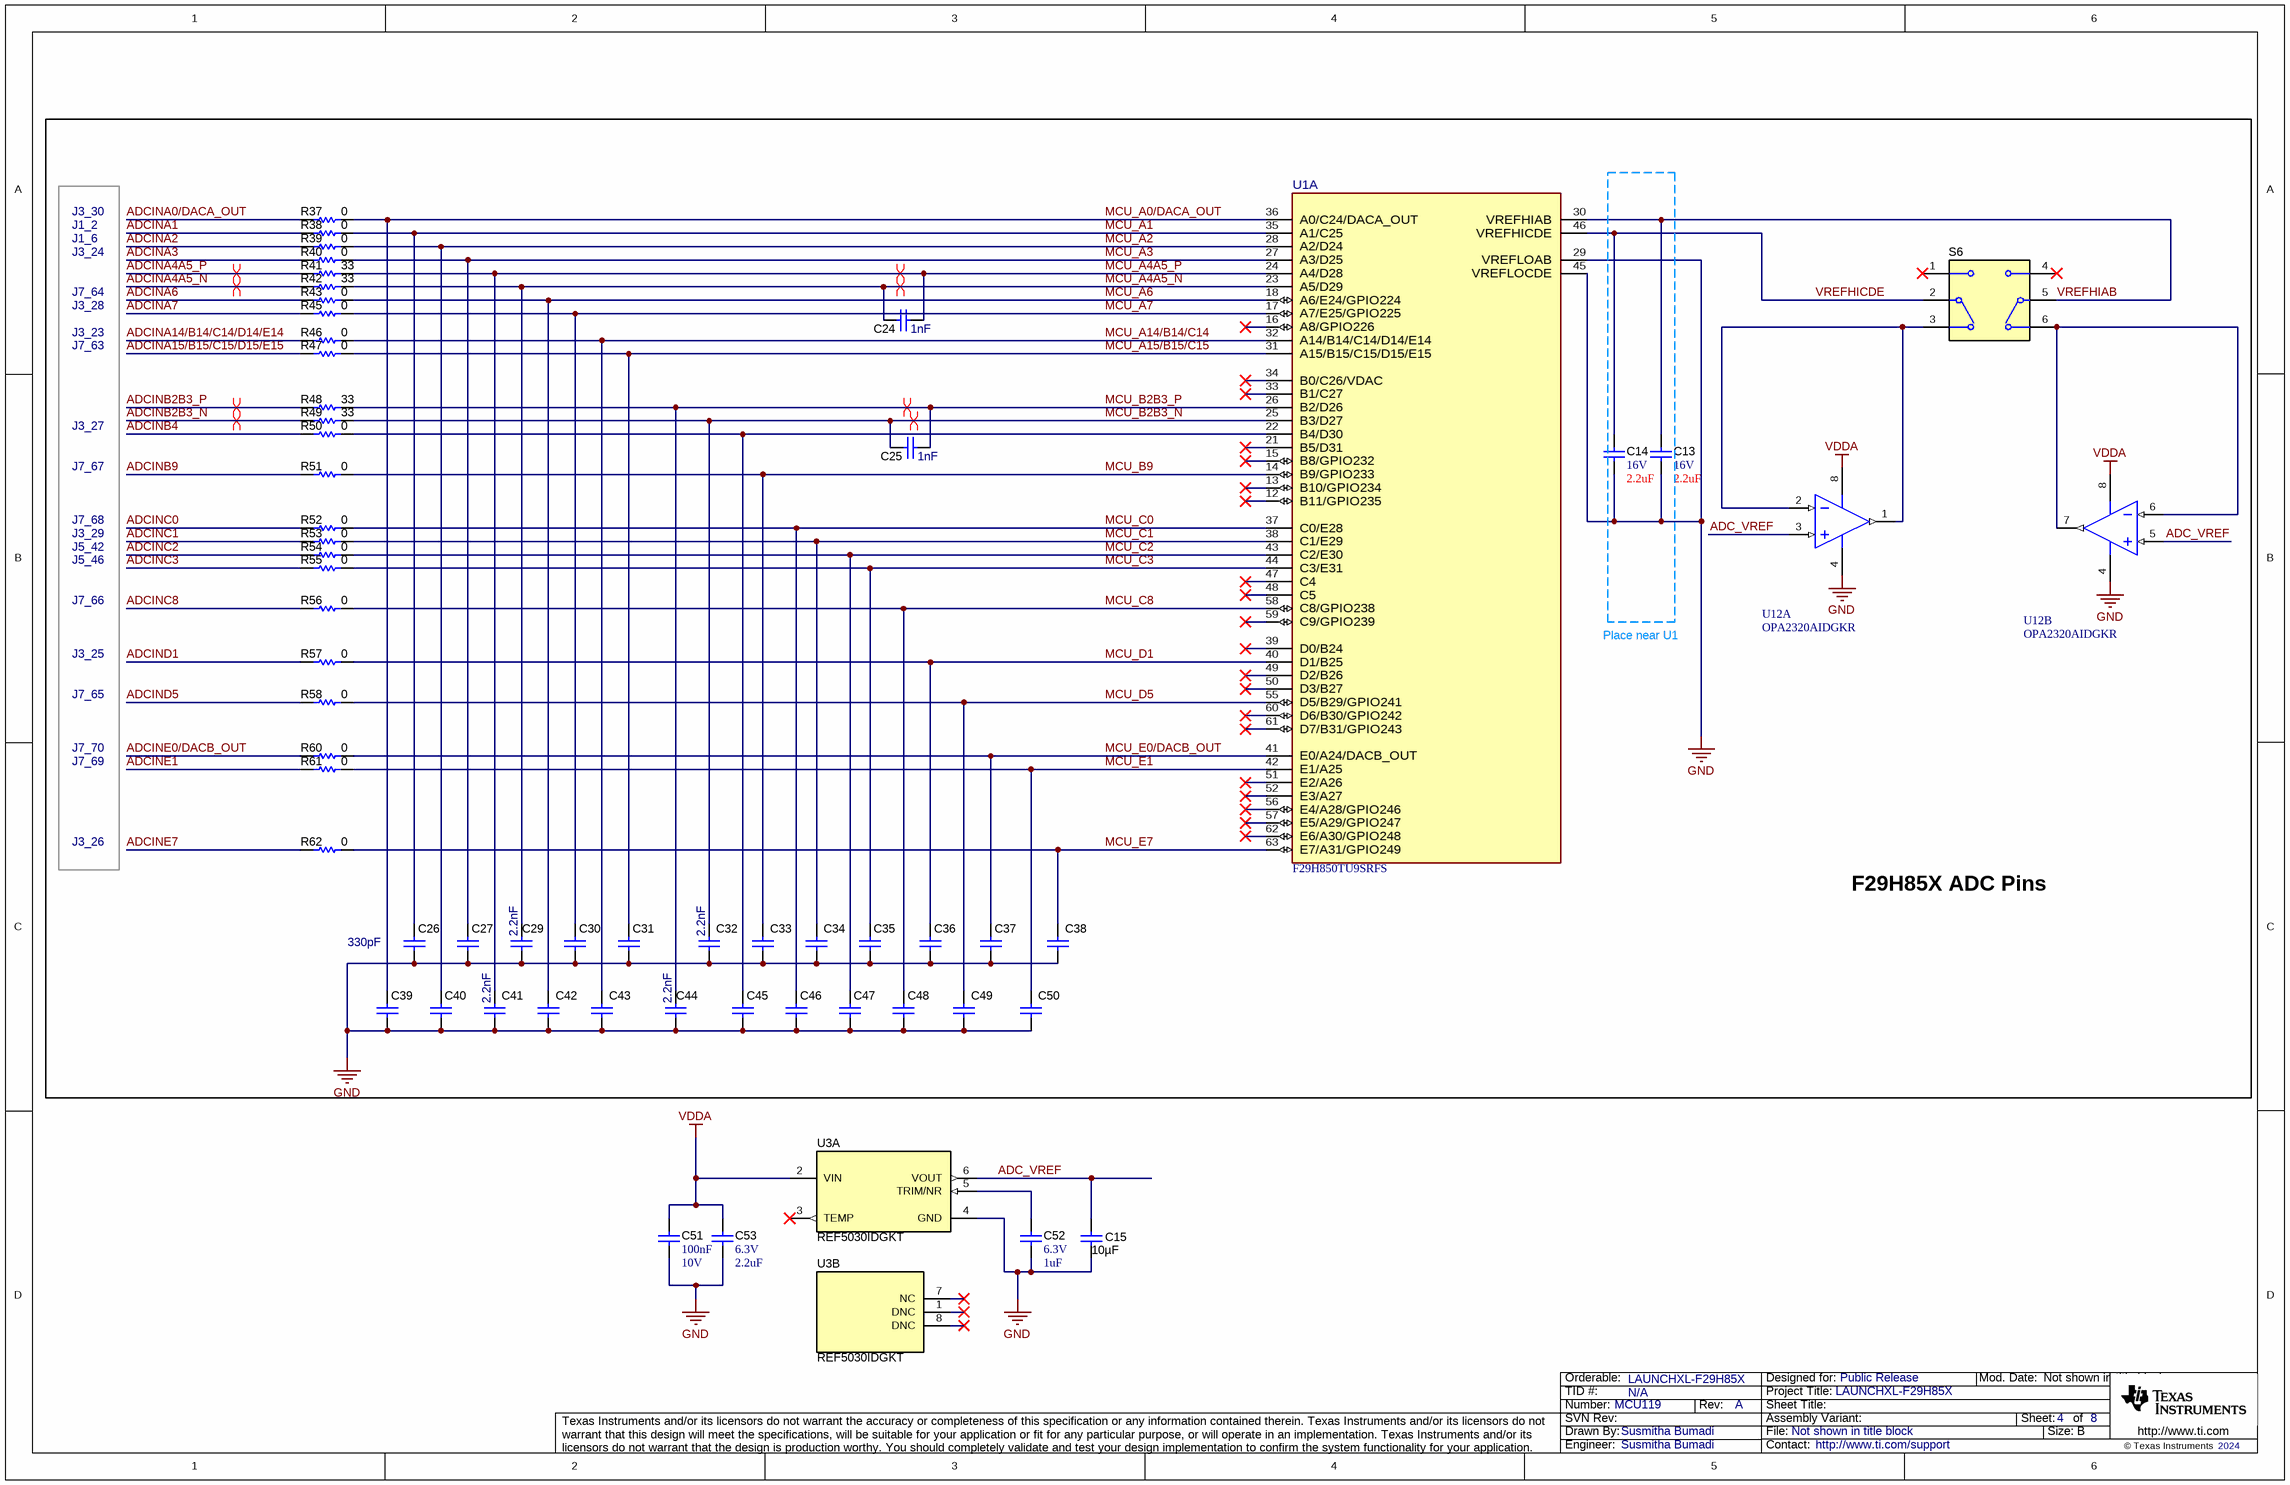
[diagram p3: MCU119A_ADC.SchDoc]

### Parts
C13  VDC_V: 16V  ValueDisplayed: 2.2uF  [0603]  (hidden comment: 885012106018)
C14  VDC_V: 16V  ValueDisplayed: 2.2uF  [0603]  (hidden comment: 885012106018)
C15  ValueDisplayed: 10µF  [0402_080]  (hidden comment: 0402ZD106MAT2A)
C24  value 1nF  [0603]  (hidden comment: C0603C102J5GACTU)
C25  value 1nF  [0603]  (hidden comment: C0603C102J5GACTU)
C26  value 330pF  [0402]  (hidden comment: GRM1555C1H331JA01D)
C27  GRM1555C1H331JA01D  [0402]  (value not drawn)
C29  value 2.2nF  [0603]  (hidden comment: CL05B222JB5NNNC)
C30  GRM1555C1H331JA01D  [0402]  (value not drawn)
C31  GRM1555C1H331JA01D  [0402]  (value not drawn)
C32  value 2.2nF  [0603]  (hidden comment: CL05B222JB5NNNC)
C33  GRM1555C1H331JA01D  [0402]  (value not drawn)
C34  GRM1555C1H331JA01D  [0402]  (value not drawn)
C35  GRM1555C1H331JA01D  [0402]  (value not drawn)
C36  GRM1555C1H331JA01D  [0402]  (value not drawn)
C37  GRM1555C1H331JA01D  [0402]  (value not drawn)
C38  GRM1555C1H331JA01D  [0402]  (value not drawn)
C39  GRM1555C1H331JA01D  [0402]  (value not drawn)
C40  GRM1555C1H331JA01D  [0402]  (value not drawn)
C41  value 2.2nF  [0603]  (hidden comment: CL05B222JB5NNNC)
C42  GRM1555C1H331JA01D  [0402]  (value not drawn)
C43  GRM1555C1H331JA01D  [0402]  (value not drawn)
C44  value 2.2nF  [0603]  (hidden comment: CL05B222JB5NNNC)
C45  GRM1555C1H331JA01D  [0402]  (value not drawn)
C46  GRM1555C1H331JA01D  [0402]  (value not drawn)
C47  GRM1555C1H331JA01D  [0402]  (value not drawn)
C48  GRM1555C1H331JA01D  [0402]  (value not drawn)
C49  GRM1555C1H331JA01D  [0402]  (value not drawn)
C50  GRM1555C1H331JA01D  [0402]  (value not drawn)
C51  Cap_F: 100nF  VDC_V: 10V  [0603]  (hidden comment: C0603C104K8RACTU)
C52  VDC_V: 6.3V  ValueDisplayed: 1uF  [0603]  (hidden comment: C0603C105Z9VACTU)
C53  VDC_V: 6.3V  ValueDisplayed: 2.2uF  [0603]  (hidden comment: C0603C225K9PACTU)
R37  ValueDisplayed: 0  [0402]  (hidden comment: RC0402JR-070RL)
R38  ValueDisplayed: 0  [0402]  (hidden comment: RC0402JR-070RL)
R39  ValueDisplayed: 0  [0402]  (hidden comment: RC0402JR-070RL)
R40  ValueDisplayed: 0  [0402]  (hidden comment: RC0402JR-070RL)
R41  ValueDisplayed: 33  [0402]  (hidden comment: CRCW040233R0JNED)
R42  ValueDisplayed: 33  [0402]  (hidden comment: CRCW040233R0JNED)
R43  ValueDisplayed: 0  [0402]  (hidden comment: RC0402JR-070RL)
R45  ValueDisplayed: 0  [0402]  (hidden comment: RC0402JR-070RL)
R46  ValueDisplayed: 0  [0402]  (hidden comment: RC0402JR-070RL)
R47  ValueDisplayed: 0  [0402]  (hidden comment: RC0402JR-070RL)
R48  ValueDisplayed: 33  [0402]  (hidden comment: CRCW040233R0JNED)
R49  ValueDisplayed: 33  [0402]  (hidden comment: CRCW040233R0JNED)
R50  ValueDisplayed: 0  [0402]  (hidden comment: RC0402JR-070RL)
R51  ValueDisplayed: 0  [0402]  (hidden comment: RC0402JR-070RL)
R52  ValueDisplayed: 0  [0402]  (hidden comment: RC0402JR-070RL)
R53  ValueDisplayed: 0  [0402]  (hidden comment: RC0402JR-070RL)
R54  ValueDisplayed: 0  [0402]  (hidden comment: RC0402JR-070RL)
R55  ValueDisplayed: 0  [0402]  (hidden comment: RC0402JR-070RL)
R56  ValueDisplayed: 0  [0402]  (hidden comment: RC0402JR-070RL)
R57  ValueDisplayed: 0  [0402]  (hidden comment: RC0402JR-070RL)
R58  ValueDisplayed: 0  [0402]  (hidden comment: RC0402JR-070RL)
R60  ValueDisplayed: 0  [0402]  (hidden comment: RC0402JR-070RL)
R61  ValueDisplayed: 0  [0402]  (hidden comment: RC0402JR-070RL)
R62  ValueDisplayed: 0  [0402]  (hidden comment: RC0402JR-070RL)
S6  CAS-D20TA  [SW_CAS-D20TA]  (value not drawn)
U1  F29H850TU9SRFS  [RFS0144A-MFG]  (part A of 4)
U3  REF5030IDGKT  [DGK0008A_N]  (parts A,B of 2)
U12  OPA2320AIDGKR  [DGK0008A_N]  (parts A,B of 2)

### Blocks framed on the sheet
F29H85X ADC Pins: C13 C14 C24-C27 C29-C50 R37-R43 R45-R58 R60-R62 S6 U1 U12

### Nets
GND: C13.2 C14.2 C15.2 C26.2 C27.2 C29.1 C30.2 C31.2 C32.1 C33.2 C34.2 C35.2 C36.2 C37.2 C38.2 C39.2 C40.2 C41.1 C42.2 C43.2 C44.1 C45.2 C46.2 C47.2 C48.2 C49.2 C50.2 C51.2 C52.2 C53.2 U1.29(VREFLOAB) U1.45(VREFLOCDE) U3.4(GND) U12.4(V-)
VDDA: C51.1 C53.1 U3.2(VIN) U12.8(V+)
ADC_VREF: C15.1 U3.6(VOUT) U12.3(IN_A+) U12.5(IN_B+)
ADCINA0/DACA_OUT: R37.1
ADCINA1: R38.1
ADCINA2: R39.1
ADCINA3: R40.1
ADCINA4A5_N: R42.1
ADCINA4A5_P: R41.1
ADCINA6: R43.1
ADCINA7: R45.1
ADCINA14/B14/C14/D14/E14: R46.1
ADCINA15/B15/C15/D15/E15: R47.1
ADCINB2B3_N: R49.1
ADCINB2B3_P: R48.1
ADCINB4: R50.1
ADCINB9: R51.1
ADCINC0: R52.1
ADCINC1: R53.1
ADCINC2: R54.1
ADCINC3: R55.1
ADCINC8: R56.1
ADCIND1: R57.1
ADCIND5: R58.1
ADCINE0/DACB_OUT: R60.1
ADCINE1: R61.1
ADCINE7: R62.1
MCU_A0/DACA_OUT: C39.1 R37.2 U1.36(A0/C24/DACA_OUT)
MCU_A1: C26.1 R38.2 U1.35(A1/C25)
MCU_A2: C40.1 R39.2 U1.28(A2/D24)
MCU_A3: C27.1 R40.2 U1.27(A3/D25)
MCU_A4A5_N: C24.1 C29.2 R42.2 U1.23(A5/D29)
MCU_A4A5_P: C24.2 C41.2 R41.2 U1.24(A4/D28)
MCU_A6: C42.1 R43.2 U1.18(A6/E24/GPIO224)
MCU_A7: C30.1 R45.2 U1.17(A7/E25/GPIO225)
MCU_A14/B14/C14: C43.1 R46.2 U1.32(A14/B14/C14/D14/E14)
MCU_A15/B15/C15: C31.1 R47.2 U1.31(A15/B15/C15/D15/E15)
MCU_B2B3_N: C25.1 C32.2 R49.2 U1.25(B3/D27)
MCU_B2B3_P: C25.2 C44.2 R48.2 U1.26(B2/D26)
MCU_B9: C33.1 R51.2 U1.14(B9/GPIO233)
MCU_C0: C46.1 R52.2 U1.37(C0/E28)
MCU_C1: C34.1 R53.2 U1.38(C1/E29)
MCU_C2: C47.1 R54.2 U1.43(C2/E30)
MCU_C3: C35.1 R55.2 U1.44(C3/E31)
MCU_C8: C48.1 R56.2 U1.58(C8/GPIO238)
MCU_D1: C36.1 R57.2 U1.40(D1/B25)
MCU_D5: C49.1 R58.2 U1.55(D5/B29/GPIO241)
MCU_E0/DACB_OUT: C37.1 R60.2 U1.41(E0/A24/DACB_OUT)
MCU_E1: C50.1 R61.2 U1.42(E1/A25)
MCU_E7: C38.1 R62.2 U1.63(E7/A31/GPIO249)
VREFHIAB: C13.1 S6.5(C) U1.30(VREFHIAB)
VREFHICDE: C14.1 S6.2(C) U1.46(VREFHICDE)
NetC45_1: C45.1 R50.2 U1.22(B4/D30)
NetC52_1: C52.1 U3.5(TRIM/NR)
NetS6_3: S6.3 U12.1(OUT_A) U12.2(IN_A-)
NetS6_6: S6.6 U12.6(IN_B-) U12.7(OUT_B)

Not connected (* = marked no-connect by the designer): S6 1* 4*; U1 12(B11/GPIO235)* 13(B10/GPIO234)* 15(B8/GPIO232)* 16(A8/GPIO226)* 21(B5/D31)* 33(B1/C27)* 34(B0/C26/VDAC)* 39(D0/B24)* 47(C4)* 48(C5)* 49(D2/B26)* 50(D3/B27)* 51(E2/A26)* 52(E3/A27)* 56(E4/A28/GPIO246)* 57(E5/A29/GPIO247)* 59(C9/GPIO239)* 60(D6/B30/GPIO242)* 61(D7/B31/GPIO243)* 62(E6/A30/GPIO248)*; U3 1(DNC)* 3(TEMP)* 7(NC)* 8(DNC)*

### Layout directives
differential pair: ADCINA4A5_N, ADCINA4A5_P, ADCINB2B3_N, ADCINB2B3_P, MCU_A4A5_N, MCU_A4A5_P, MCU_B2B3_N, MCU_B2B3_P

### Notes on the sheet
- J1_2
- J3_30
- J1_6
- J7_64
- J3_24
- J3_28
- J3_23
- J7_63
- J3_27
- J7_67
- J3_29
- J5_46
- J7_68
- J5_42
- J7_66
- (near U1) Place near U1
- J3_25
- J7_65
- J7_69
- J7_70
- J3_26

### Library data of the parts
C13 C14 = CMP-0007341-5: CAP, CERM, 2.2 uF, 16 V, +/- 20%, X5R, 0603; Manufacturer: MuRata; PartNumber: GRM188R61C475KAAJ; TaMin_C: -55°C; Polarized: N; SizeAreaWB_mm2: 4.68; Value1: Unknown; U/M: EA; Value: 4.7uF; TaMax_C: 85°C; Tolerance_%: 10%; SizeZ_mm: 1; SizeX_mm: 1.6; SizeY_mm: 0.8; SizeArea_mm2: 1.28; Cap_F: 4.7µF; AEC Category: Q200
C15 = CMP-0078623-1: CAP, CERM, 10 µF, 10 V,+/- 20%, X5R, 0402; Manufacturer: AVX; SizeAreaWB_mm2: 3; SizeArea_mm2: 0.5; AEC Qualified: N; AEC Category: Q200; Value: 10uF; TaMax_C: 85°C; SizeZ_mm: 0.8; TaMin_C: -55°C; VDC_V: 10V; U/M: EA; SizeX_mm: 1
C24 C25 = CMP-0006920-4: CAP, CERM, 1000 pF, 50 V, +/- 5%, C0G/NP0, 0603; Manufacturer: Kemet; PartNumber: C0603C331J5GACTU; TaMin_C: -55°C; Polarized: N; SizeAreaWB_mm2: 4.68; Value1: Unknown; U/M: EA; TaMax_C: 125°C; SizeZ_mm: 1; SizeX_mm: 1.6; SizeY_mm: 0.8; Value2: 50V; SizeArea_mm2: 1.28; Cap_F: 330pF; AEC Category: Q200
C26 = CMP-0006456-2: CAP, CERM, 330 pF, 50 V, +/- 5%, C0G/NP0, 0402; Manufacturer: MuRata; TaMin_C: -55°C; Polarized: N; SizeAreaWB_mm2: 3; Value1: Unknown; U/M: EA; TaMax_C: 125°C; SizeZ_mm: 0.6; SizeX_mm: 1; SizeY_mm: 0.5; Value2: 50V; AEC Category: Q200
C27 C30 C31 C33-C40 C42 C43 C45-C50 = CMP-0006456-2: CAP, CERM, 330 pF, 50 V, +/- 5%, C0G/NP0, 0402; Manufacturer: MuRata; TaMin_C: -55°C; Polarized: N; SizeAreaWB_mm2: 3; Value1: Unknown; U/M: EA; Value: 330pF; TaMax_C: 125°C; SizeZ_mm: 0.6; SizeX_mm: 1; SizeY_mm: 0.5; Value2: 50V; AEC Category: Q200
C29 C32 C41 C44 = CMP-0006920-4: CAP, CERM, 2200 pF, 50 V, +/- 5%, X7R, 0402; Manufacturer: Kemet; PartNumber: C0603C331J5GACTU; TaMin_C: -55°C; Polarized: N; TempCo: C0G/NP0; SizeAreaWB_mm2: 4.68; Value1: Unknown; U/M: EA; TaMax_C: 125°C; SizeZ_mm: 1; SizeX_mm: 1.6; SizeY_mm: 0.8; Value2: 50V; SizeArea_mm2: 1.28; Cap_F: 330pF; AEC Category: Q200
C51 = CMP-0006862-5: CAP, CERM, 0.1 uF, 10 V, +/- 10%, X7R, 0603; Manufacturer: Kemet; TaMin_C: -55°C; Polarized: N; SizeAreaWB_mm2: 4.68; Value1: Unknown; U/M: EA; Value: 0.1uF; TaMax_C: 125°C; SizeZ_mm: 1; SizeX_mm: 1.6; SizeY_mm: 0.8; SizeArea_mm2: 1.28; AEC Category: Q200
C52 = CMP-0006871-4: CAP, CERM, 1 uF, 6.3 V, +80/-20%, Y5V, 0603; Manufacturer: Kemet; TaMin_C: -30°C; Polarized: N; SizeAreaWB_mm2: 4.68; Value1: Unknown; U/M: EA; Value: 1uF; TaMax_C: 85°C; Tolerance_%: 80%; SizeZ_mm: 1; SizeX_mm: 1.6; SizeY_mm: 0.8; SizeArea_mm2: 1.28; Cap_F: 1µF; AEC Category: Q200
C53 = CMP-0006907-5: CAP, CERM, 2.2 uF, 6.3 V, +/- 10%, X5R, 0603; Manufacturer: Kemet; TaMin_C: -55°C; Polarized: N; SizeAreaWB_mm2: 4.68; Value1: Unknown; U/M: EA; Value: 2.2uF; TaMax_C: 85°C; SizeZ_mm: 1; SizeX_mm: 1.6; SizeY_mm: 0.8; SizeArea_mm2: 1.28; Cap_F: 2.2µF; AEC Category: Q200
R37-R40 R43 R45-R47 R50-R58 R60-R62 = CMP-0027004-2: RES, 0, 5%, 0.063 W, 0402; Manufacturer: Yageo America; Power_W: 63mW; TempCo: 200 ppm/C; Value_Code: 0000; U/M: EA; Value: 0; EIA_Code: E24; SizeX_mm: 1; SizeY_mm: 0.5; SizeZ_mm: 0.6; Value2: 0.063W; VDC_V: 50V; AEC Category: Q200
R41 R42 R48 R49 = CMP-0027004-2: RES, 33, 5%, 0.063 W, AEC-Q200 Grade 0, 0402; Manufacturer: Yageo America; PartNumber: RC0402JR-070RL; Power_W: 63mW; TempCo: 200 ppm/C; Value_Code: 0000; U/M: EA; Value: 0; EIA_Code: E24; SizeX_mm: 1; SizeY_mm: 0.5; SizeZ_mm: 0.6; Value2: 0.063W; VDC_V: 50V; AEC Category: Q200
S6 = CMP-0002233-1: Switch, Dual SPDT,  2 Pos, 0.1A, 6VDC, SMD; Manufacturer: Copal Electronics; CurrentRating_mA: 100A; SwitchFunction: On-On; VDC_V: 6V; PositionCount: 2
U1 = CMP-0121584-3: as U1 on sheet MCU119A_F29H85X_Device
U3 = CMP-0032596-2: Low Noise, Very Low Drift, Precision Series Voltage Reference, DGK0008A (VSSOP-8); Manufacturer: Texas Instruments; Temp Coeff(Max)(ppm/ degree C): 3; Iout/Iz(Max)(mA): 10; VI(Min)(V): 3.2; Eco-Plan: Green (RoHS & no Sb/Br); Initial Accuracy @ 25/deg C(%): 0.05; Iq(Max)(uA): 1000; VI(Max)(V): 18; Rating: Catalog; AEC Category: Q200; AEC Qualified: N; CompType: IC; SizeAreaWB_mm2: 23.6; SizeArea_mm2: 14.7; SizeX_mm: 4.9; SizeZ_mm: 1.1
U12 = CMP-0040679-2: Precision, Zero-Crossover, 20MHz, 0.9pA Ib, RRIO, CMOS Operational Amplifier, DGK0008A (VSSOP-8); Manufacturer: Texas Instruments; Offset Drift(Typ)(uV/C): 1.5; Vio (25C)(Max)(mV): 0.15; Total Supply Voltage(Max)(+5V is 5, +/-5V is 10): 5.5; Iq per channel(Max)(mA): 1.6; IIB(Max)(pA): 400; Slew Rate(Typ)(V/us): 10; Sub Family: High Output Current Amplifier (>=50mA), Low Input Bias Current Amp (<=10pA), Low Noise Amp (<=10nV/rtHz), Low Offset Voltage Amplifier (<=500uV), Low Supply Voltage Amplifier (<=2.7V), Precision Amplifier; CMRR(Min)(dB): 100; Total Supply Voltage(Min)(+5V is 5, +/-5V is 10): 1.8; Number of Channels: 2; Eco-Plan: Green (RoHS & no Sb/Br); Vn at 1kHz(Typ)(nV/rtHz): 8.5; AEC Category: Q200; AEC Qualified: N; CompType: IC; SizeAreaWB_mm2: 23.6; SizeArea_mm2: 14.7; SizeX_mm: 4.9; SizeY_mm: 3; SizeZ_mm: 1.1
